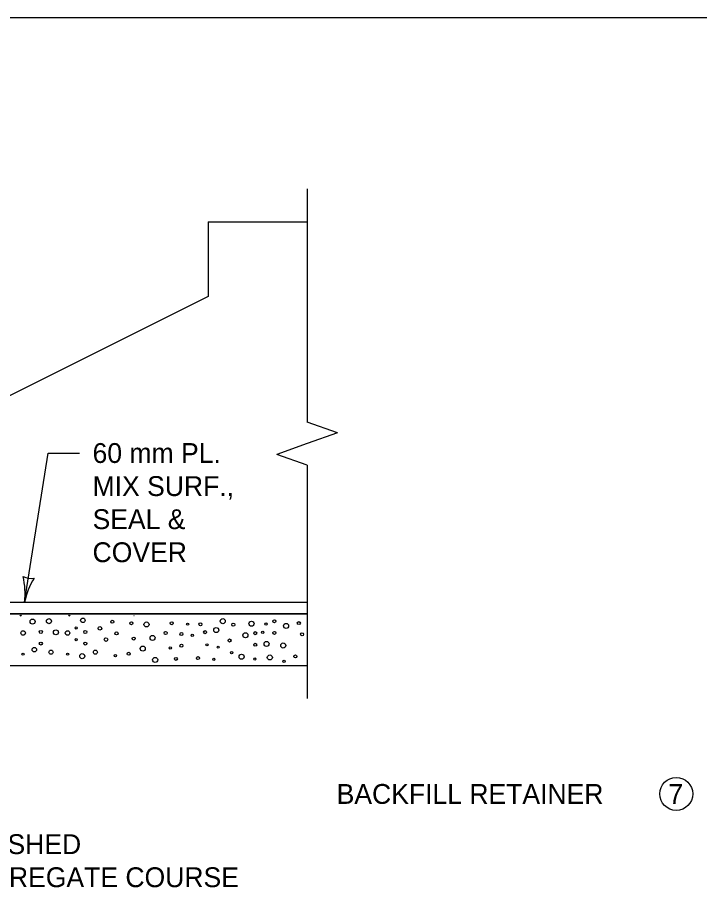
# Model space of a CAD drawing. Extents: x 49991.4 to 50021, y 49987.6 to 50011.4.
# Drawn here: x 50009.692 to 50011.755, y 49989.4 to 49992.055 of the extents above; entities that cross this region are included whole.
import ezdxf

# ---------------------------------------------------------------- set-up
doc = ezdxf.new("R2010")
doc.units = 0
for name, color, linetype in [('Level 1', 7, 'Continuous'), ('Level 2', 7, 'Continuous'), ('Level 3', 7, 'Continuous'), ('Level 6', 7, 'Continuous')]:
    doc.layers.add(name, color=color, linetype=linetype)

msp = doc.modelspace()

# ---------------------------------------------------------------- linework, layer by layer
at = {"layer": 'Level 1'}
for p, q in [((50010.2683, 49991.4374), (50010.2683, 49991.2116)), ((50010.2683, 49991.4374), (50010.568, 49991.4374)), ((50010.2683, 49991.2116), (50008.4885, 49990.3217)), ((50008.6055, 49990.287), (50010.568, 49990.287)), ((50009.303, 49990.287), (50010.568, 49990.287)), ((50010.568, 49990.287), (50010.568, 49990.2515)), ((50008.6055, 49990.2515), (50010.568, 49990.2515)), ((50010.568, 49990.2515), (50009.303, 49990.2515)), ((50008.4885, 49990.0955), (50010.568, 49990.0955))]:
    msp.add_line(p, q, dxfattribs=at)
msp.add_lwpolyline([(49999.5613, 49992.0549), (50014.5211, 49992.0549), (50014.5211, 49988.3552), (49999.5613, 49988.3552)], close=True, dxfattribs=at)
for centre, radius in [((50009.8898, 49990.2319), 0.00684), ((50009.7377, 49990.2282), 0.00766), ((50009.7872, 49990.2296), 0.00765), ((50009.8694, 49990.2092), 0.00341), ((50009.9413, 49990.2078), 0.00552), ((50009.9787, 49990.2278), 0.0046), ((50010.0364, 49990.2234), 0.0046), ((50010.0821, 49990.2196), 0.00766), ((50010.1583, 49990.2234), 0.0046), ((50010.2066, 49990.2205), 0.00341), ((50010.2454, 49990.2202), 0.0046), ((50010.3127, 49990.2295), 0.00766), ((50010.3446, 49990.2189), 0.0046), ((50010.3997, 49990.222), 0.00766), ((50010.4434, 49990.2209), 0.00341), ((50010.4688, 49990.2294), 0.0046), ((50010.5043, 49990.2151), 0.00766), ((50010.5429, 49990.2236), 0.0046), ((50009.7089, 49990.1939), 0.00684), ((50009.7625, 49990.197), 0.0046), ((50009.8083, 49990.1958), 0.00765), ((50009.8434, 49990.1939), 0.00684), ((50009.897, 49990.197), 0.0046), ((50009.9914, 49990.1926), 0.0046), ((50010.1004, 49990.1788), 0.00766), ((50010.14, 49990.1938), 0.0046), ((50010.1879, 49990.1906), 0.0046), ((50010.2207, 49990.1868), 0.00341), ((50010.2595, 49990.1963), 0.0046), ((50010.293, 49990.2028), 0.00766), ((50010.3814, 49990.1869), 0.00766), ((50010.4109, 49990.1933), 0.0046), ((50010.4336, 49990.1956), 0.00341), ((50010.4688, 49990.1942), 0.0046), ((50010.5528, 49990.1898), 0.0046), ((50009.7625, 49990.1618), 0.0046), ((50009.8694, 49990.174), 0.00341), ((50009.897, 49990.1618), 0.0046), ((50009.9596, 49990.174), 0.00552), ((50010.0435, 49990.177), 0.0046), ((50010.1879, 49990.1554), 0.0046), ((50010.265, 49990.1581), 0.00341), ((50010.3334, 49990.1711), 0.0046), ((50010.4109, 49990.1581), 0.0046), ((50010.4452, 49990.1607), 0.00766), ((50010.4959, 49990.156), 0.00766), ((50009.7089, 49990.1298), 0.00341), ((50009.7427, 49990.1432), 0.00684), ((50009.7932, 49990.1359), 0.00613), ((50009.8434, 49990.1298), 0.00341), ((50009.9276, 49990.1359), 0.00613), ((50010.0283, 49990.131), 0.0046), ((50010.0709, 49990.1466), 0.00766), ((50010.1542, 49990.1488), 0.00341), ((50010.299, 49990.1509), 0.00341), ((50010.3395, 49990.1343), 0.00341), ((50009.8878, 49990.1237), 0.00766), ((50009.9882, 49990.1252), 0.00341), ((50010.1084, 49990.1122), 0.00766), ((50010.171, 49990.1154), 0.0046), ((50010.2379, 49990.1179), 0.0046), ((50010.2859, 49990.1138), 0.00341), ((50010.3698, 49990.122), 0.00766), ((50010.4098, 49990.1149), 0.00341), ((50010.4552, 49990.1198), 0.00766), ((50010.4981, 49990.1084), 0.00341), ((50010.5325, 49990.1228), 0.0046)]:
    msp.add_circle(centre, radius, dxfattribs=at)
for centre, radius, start, end in [((50009.7017, 49990.2487), 0.00283, 211.7965, 328.2035), ((50009.8488, 49990.2487), 0.00283, 211.7965, 328.2035), ((50010.0441, 49990.2434), 0.00277, 77.9755, 102.0245)]:
    msp.add_arc(centre, radius, start, end, dxfattribs=at)
at = {"layer": 'Level 2'}
msp.add_circle((50011.6846, 49989.7071), 0.05, dxfattribs=at)
at = {"layer": 'Level 3'}
for p, q in [((50009.7136, 49990.287), (50009.7845, 49990.738)), ((50009.7845, 49990.738), (50009.879, 49990.738))]:
    msp.add_line(p, q, dxfattribs=at)
for centre, radius, start, end in [((50009.7335, 49990.4137), 0.0548, 243.2047, 278.927), ((50009.482, 49990.3118), 0.233, 353.8932, 13.143), ((50009.9316, 49990.2435), 0.2223, 148.5219, 168.7054)]:
    msp.add_arc(centre, radius, start, end, dxfattribs=at)
at = {"layer": 'Level 6'}
for p, q in [((50010.568, 49991.5374), (50010.568, 49990.8312)), ((50010.6594, 49990.7988), (50010.568, 49990.8312)), ((50010.6594, 49990.7988), (50010.568, 49990.7664)), ((50010.568, 49990.7664), (50010.4766, 49990.734)), ((50010.568, 49990.7016), (50010.4766, 49990.734)), ((50010.568, 49990.7016), (50010.568, 49989.9955))]:
    msp.add_line(p, q, dxfattribs=at)

# ---------------------------------------------------------------- texts
at = {"layer": 'Level 2'}
for s, p in [('60 mm PL.', (50009.919, 49990.708)), ('MIX SURF.,', (50009.919, 49990.608)), ('SEAL &', (50009.919, 49990.508)), ('COVER', (50009.919, 49990.408)), ('BACKFILL RETAINER', (50010.6573, 49989.6771)), ('7', (50011.6608, 49989.6771)), ('CRUSHED', (50009.4878, 49989.5252)), ('AGGREGATE COURSE', (50009.4878, 49989.4252))]:
    msp.add_text(s, height=0.06, dxfattribs=at).set_placement(p)

doc.saveas('drawing.dxf')
